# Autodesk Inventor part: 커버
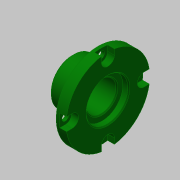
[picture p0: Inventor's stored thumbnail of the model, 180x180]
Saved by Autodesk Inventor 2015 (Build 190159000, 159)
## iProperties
Created: 2019-10
Part Number: 커버
Material: 알루미늄 6061
Document SubType Name: Modeling
Designer: mduedu
Density: 1 g/cm^3
Appearance: 진녹색
Author: mduedu
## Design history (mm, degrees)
sketch "스케치1"
  geometry: L1 (0, 0)-(-18, 0); L2 (-18, 0)-(-18, 11.5); L3 (-18, 11.5)-(-5, 11.5); L4 (-5, 11.5)-(-5, 21); L5 (-5, 21)-(0, 21); L6 (0, 21)-(0, 0)
  constraints: 12 end point, 3 parallel, 2 perpendicular, 1 horizontal
  dimensions: "d0" = 18 distance of L1.start L1.end; "d1" = 42 diameter of L5 L1; "d2" = 23 diameter of L3 L1; "d3" = 13 distance of L2.end L3.end
revolve "회전1" sketch "스케치1" stored, may be unused: angle "d4" = 90 deg
hole "구멍1" diameter "d7" = 15; stored, may be unused: countersink angle "d11" = 90 deg, drill point angle "d13" = 118 deg; dims "d5" = 10, "d6" = 10, "d8" = 6, "d9" = 21, "d10" = 3, "d12" = 8
chamfer "모따기1" distance "d14" = 1; stored, may be unused: second distance "d15" = 2, angle "d16" = 45 deg
sketch "스케치2" dims "d17" = 36
  geometry: 6 further points
  constraints: 2 vertical alignment, 1 coincident, 7 other
  dimensions: "d20" = 360 deg dimension on point (0, 0) point (0, 18) (derived)
sketch "스케치3"
  geometry: 4 further points
  constraints: 4 other
hole "구멍2" sketch "스케치3" at (-18, 0), (0, -18), (18, 0), (0, 18) diameter "d22" = 3.4; stored, may be unused: countersink angle "d26" = 90 deg, drill point angle "d28" = 0 deg; dims "d23" = 6, "d24" = 6.5, "d25" = 3.4, "d27" = 8
sketch "스케치4"
  geometry: L1 (-21.25, 20.747)-(-21.25, 18); L2 (-14.75, 18)-(-14.75, 20.747); A1 r 3.25 centre (-18, 18) between (-19.349, 20.957) and (-16.651, 20.957) reference; A2 r 21 centre (-18, 0) between (-19.349, 20.957) and (-38.957, 1.349) reference; A3 r 21 centre (-18, 0) between (2.957, 1.349) and (-16.651, 20.957) reference; A4 r 21 centre (-18, 0) between (-14.75, 20.747) and (-21.25, 20.747); A5 r 3.25 centre (-18, 18) between (-21.25, 18) and (-14.75, 18); 1 further point
  constraints: 8 point on circle, 4 end point, 2 centre point, 2 coincident, 2 tangent, 1 parallel, 1 vertical
extrude "돌출1" cut sketch "스케치4" stored distance "d29" = 10; taper "d30" = 0 deg
chamfer "모따기3" distance "d37" = 0.5; stored, may be unused: second distance "d38" = 2, angle "d39" = 45 deg
chamfer "모따기4" distance "d40" = 0.5; stored, may be unused: second distance "d41" = 2, angle "d42" = 45 deg
node "솔리드1"
pattern_circular "원형 패턴1" dims angle "d32" = 360 deg
